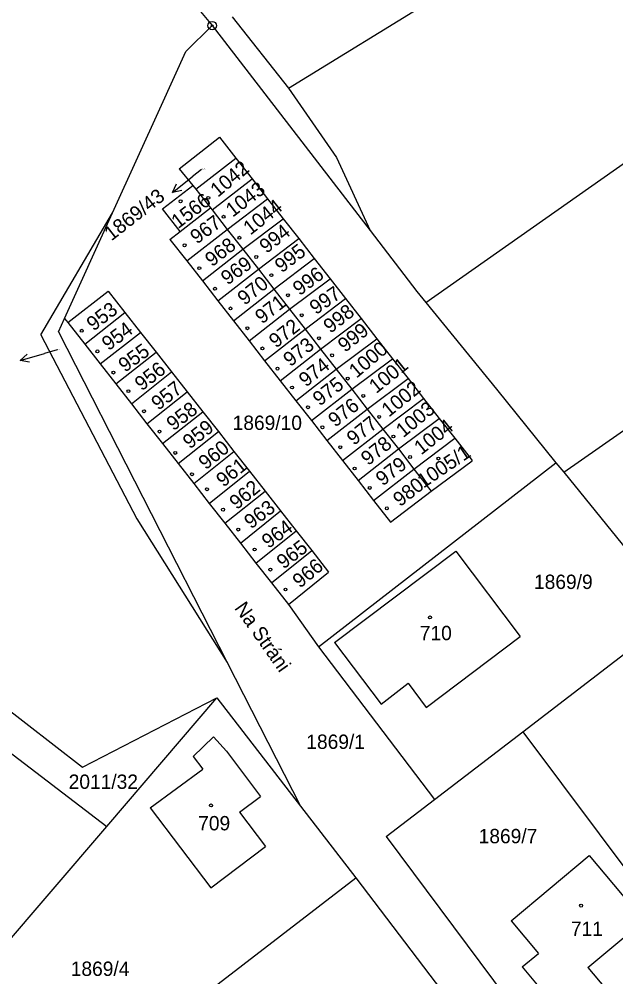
# Model space of a CAD drawing. Extents: x -763205 to -760228, y -1155311 to -1152844.
# Drawn here: x -761715.4 to -761644.6, y -1154597.9 to -1154484.3 of the extents above; entities that cross this region are included whole.
import ezdxf

# ---------------------------------------------------------------- set-up
doc = ezdxf.new("R2010")
doc.units = 0
for name, color, linetype in [('Vrstva 1', 7, 'Continuous'), ('Vrstva 15', 7, 'Continuous'), ('Vrstva 16', 7, 'Continuous'), ('Vrstva 18', 7, 'Continuous'), ('Vrstva 19', 7, 'Continuous'), ('Vrstva 24', 7, 'Continuous'), ('Vrstva 25', 7, 'Continuous'), ('Vrstva 6', 7, 'Continuous')]:
    doc.layers.add(name, color=color, linetype=linetype)

msp = doc.modelspace()

# ---------------------------------------------------------------- linework, layer by layer
at = {"layer": 'Vrstva 1'}
for p, q in [((-761717.74, -1154454.29), (-761692.49, -1154485.08)), ((-761695.63, -1154488.16), (-761692.49, -1154485.08)), ((-761692.49, -1154485.08), (-761673.78, -1154509.38)), ((-761698.5, -1154494.49), (-761695.63, -1154488.16)), ((-761704.31, -1154507.28), (-761698.5, -1154494.49)), ((-761696.42, -1154502.05), (-761691.62, -1154498.3)), ((-761691.62, -1154498.3), (-761689.69, -1154500.78)), ((-761694.43, -1154504.48), (-761689.69, -1154500.78)), ((-761689.69, -1154500.78), (-761687.77, -1154503.24)), ((-761696.42, -1154502.05), (-761694.8, -1154504.03)), ((-761692.5, -1154506.94), (-761687.77, -1154503.24)), ((-761687.77, -1154503.24), (-761685.92, -1154505.6)), ((-761698.38, -1154506.79), (-761694.8, -1154504.03)), ((-761694.8, -1154504.03), (-761694.43, -1154504.48)), ((-761694.43, -1154504.48), (-761692.69, -1154506.67)), ((-761690.7, -1154509.24), (-761685.92, -1154505.6)), ((-761685.92, -1154505.6), (-761684.08, -1154507.97)), ((-761696.28, -1154509.47), (-761698.38, -1154506.79)), ((-761696.28, -1154509.47), (-761692.69, -1154506.67)), ((-761692.69, -1154506.67), (-761692.5, -1154506.94)), ((-761692.5, -1154506.94), (-761690.7, -1154509.24)), ((-761709.98, -1154519.79), (-761704.31, -1154507.28)), ((-761688.85, -1154511.6), (-761684.08, -1154507.97)), ((-761684.08, -1154507.97), (-761682.24, -1154510.33)), ((-761697.5, -1154510.42), (-761696.28, -1154509.47)), ((-761695.5, -1154512.98), (-761690.7, -1154509.24)), ((-761690.7, -1154509.24), (-761688.85, -1154511.6)), ((-761687.01, -1154513.97), (-761682.24, -1154510.33)), ((-761682.24, -1154510.33), (-761680.4, -1154512.69)), ((-761673.78, -1154509.38), (-761668.22, -1154516.6)), ((-761697.5, -1154510.42), (-761695.5, -1154512.98)), ((-761693.66, -1154515.35), (-761688.85, -1154511.6)), ((-761688.85, -1154511.6), (-761687.01, -1154513.97)), ((-761695.5, -1154512.98), (-761693.66, -1154515.35)), ((-761685.17, -1154516.34), (-761680.4, -1154512.69)), ((-761680.4, -1154512.69), (-761678.52, -1154515.09)), ((-761691.81, -1154517.72), (-761687.01, -1154513.97)), ((-761687.01, -1154513.97), (-761685.17, -1154516.34)), ((-761693.66, -1154515.35), (-761691.81, -1154517.72)), ((-761683.32, -1154518.71), (-761678.52, -1154515.09)), ((-761678.52, -1154515.09), (-761676.68, -1154517.45)), ((-761650.83, -1154538.03), (-761619.25, -1154515.92)), ((-761709.6, -1154520.28), (-761704.83, -1154516.55)), ((-761704.83, -1154516.55), (-761702.83, -1154519.1)), ((-761689.97, -1154520.08), (-761685.17, -1154516.34)), ((-761685.17, -1154516.34), (-761683.32, -1154518.71)), ((-761668.22, -1154516.6), (-761667.18, -1154517.89)), ((-761691.81, -1154517.72), (-761689.97, -1154520.08)), ((-761681.48, -1154521.07), (-761676.68, -1154517.45)), ((-761676.68, -1154517.45), (-761674.84, -1154519.81)), ((-761667.18, -1154517.89), (-761658.81, -1154528.2)), ((-761707.6, -1154522.84), (-761702.83, -1154519.1)), ((-761702.83, -1154519.1), (-761700.99, -1154521.45)), ((-761688.12, -1154522.45), (-761683.32, -1154518.71)), ((-761683.32, -1154518.71), (-761681.48, -1154521.07)), ((-761710.7, -1154521.38), (-761709.98, -1154519.79)), ((-761709.98, -1154519.79), (-761709.6, -1154520.28)), ((-761709.6, -1154520.28), (-761707.6, -1154522.84)), ((-761689.97, -1154520.08), (-761688.12, -1154522.45)), ((-761679.64, -1154523.45), (-761674.84, -1154519.81)), ((-761674.84, -1154519.81), (-761672.96, -1154522.21)), ((-761710.7, -1154521.38), (-761690.71, -1154560.61)), ((-761705.76, -1154525.2), (-761700.99, -1154521.45)), ((-761700.99, -1154521.45), (-761699.14, -1154523.8)), ((-761686.28, -1154524.81), (-761681.48, -1154521.07)), ((-761681.48, -1154521.07), (-761679.64, -1154523.45)), ((-761707.6, -1154522.84), (-761705.76, -1154525.2)), ((-761688.12, -1154522.45), (-761686.28, -1154524.81)), ((-761677.8, -1154525.81), (-761672.96, -1154522.21)), ((-761672.96, -1154522.21), (-761671.12, -1154524.57)), ((-761703.91, -1154527.56), (-761699.14, -1154523.8)), ((-761699.14, -1154523.8), (-761697.3, -1154526.15)), ((-761684.43, -1154527.18), (-761679.64, -1154523.45)), ((-761679.64, -1154523.45), (-761677.8, -1154525.81)), ((-761686.28, -1154524.81), (-761684.43, -1154527.18)), ((-761675.95, -1154528.18), (-761671.12, -1154524.57)), ((-761671.12, -1154524.57), (-761669.28, -1154526.93)), ((-761705.76, -1154525.2), (-761703.91, -1154527.56)), ((-761702.07, -1154529.92), (-761697.3, -1154526.15)), ((-761697.3, -1154526.15), (-761695.45, -1154528.51)), ((-761682.58, -1154529.55), (-761677.8, -1154525.81)), ((-761677.8, -1154525.81), (-761675.95, -1154528.18)), ((-761684.43, -1154527.18), (-761682.58, -1154529.55)), ((-761674.11, -1154530.54), (-761669.28, -1154526.93)), ((-761669.28, -1154526.93), (-761667.43, -1154529.29)), ((-761703.91, -1154527.56), (-761702.07, -1154529.92)), ((-761700.22, -1154532.28), (-761695.45, -1154528.51)), ((-761695.45, -1154528.51), (-761693.61, -1154530.86)), ((-761680.74, -1154531.91), (-761675.95, -1154528.18)), ((-761675.95, -1154528.18), (-761674.11, -1154530.54)), ((-761658.81, -1154528.2), (-761651.74, -1154536.91)), ((-761682.58, -1154529.55), (-761680.74, -1154531.91)), ((-761672.27, -1154532.92), (-761667.43, -1154529.29)), ((-761667.43, -1154529.29), (-761665.59, -1154531.65)), ((-761702.07, -1154529.92), (-761700.22, -1154532.28)), ((-761678.89, -1154534.28), (-761674.11, -1154530.54)), ((-761674.11, -1154530.54), (-761672.27, -1154532.92)), ((-761698.38, -1154534.64), (-761693.61, -1154530.86)), ((-761693.61, -1154530.86), (-761691.76, -1154533.21)), ((-761680.74, -1154531.91), (-761678.89, -1154534.28)), ((-761670.42, -1154535.28), (-761665.59, -1154531.65)), ((-761665.59, -1154531.65), (-761663.75, -1154534.01)), ((-761700.22, -1154532.28), (-761698.38, -1154534.64)), ((-761677.05, -1154536.64), (-761672.27, -1154532.92)), ((-761672.27, -1154532.92), (-761670.42, -1154535.28)), ((-761696.53, -1154537), (-761691.76, -1154533.21)), ((-761691.76, -1154533.21), (-761689.92, -1154535.56)), ((-761668.59, -1154537.66), (-761663.75, -1154534.01)), ((-761663.75, -1154534.01), (-761661.81, -1154536.49)), ((-761698.38, -1154534.64), (-761696.53, -1154537)), ((-761678.89, -1154534.28), (-761677.05, -1154536.64)), ((-761675.2, -1154539.01), (-761670.42, -1154535.28)), ((-761670.42, -1154535.28), (-761668.59, -1154537.66)), ((-761694.68, -1154539.37), (-761689.92, -1154535.56)), ((-761689.92, -1154535.56), (-761688.08, -1154537.91)), ((-761696.53, -1154537), (-761694.68, -1154539.37)), ((-761679.9, -1154558.73), (-761651.74, -1154536.91)), ((-761677.05, -1154536.64), (-761675.2, -1154539.01)), ((-761666.55, -1154540.27), (-761661.66, -1154536.69)), ((-761661.81, -1154536.49), (-761661.66, -1154536.69)), ((-761651.74, -1154536.91), (-761650.83, -1154538.03)), ((-761692.84, -1154541.73), (-761688.08, -1154537.91)), ((-761688.08, -1154537.91), (-761686.23, -1154540.27)), ((-761673.36, -1154541.38), (-761668.59, -1154537.66)), ((-761668.59, -1154537.66), (-761666.7, -1154540.08)), ((-761650.83, -1154538.03), (-761637.32, -1154554.68)), ((-761694.68, -1154539.37), (-761692.84, -1154541.73)), ((-761675.2, -1154539.01), (-761673.36, -1154541.38)), ((-761690.99, -1154544.09), (-761686.23, -1154540.27)), ((-761686.23, -1154540.27), (-761684.39, -1154542.62)), ((-761671.36, -1154543.94), (-761666.55, -1154540.27)), ((-761666.7, -1154540.08), (-761666.55, -1154540.27)), ((-761692.84, -1154541.73), (-761690.99, -1154544.09)), ((-761673.36, -1154541.38), (-761671.36, -1154543.94)), ((-761689.15, -1154546.45), (-761684.39, -1154542.62)), ((-761684.39, -1154542.62), (-761682.54, -1154544.97)), ((-761690.99, -1154544.09), (-761689.15, -1154546.45)), ((-761687.3, -1154548.81), (-761682.54, -1154544.97)), ((-761682.54, -1154544.97), (-761680.7, -1154547.32)), ((-761689.15, -1154546.45), (-761687.3, -1154548.81)), ((-761685.46, -1154551.17), (-761680.7, -1154547.32)), ((-761680.7, -1154547.32), (-761678.7, -1154549.87)), ((-761678, -1154558.22), (-761663.63, -1154547.38)), ((-761663.63, -1154547.38), (-761655.97, -1154557.53)), ((-761687.3, -1154548.81), (-761685.46, -1154551.17)), ((-761683.46, -1154553.73), (-761678.7, -1154549.87)), ((-761685.46, -1154551.17), (-761683.46, -1154553.73)), ((-761683.46, -1154553.73), (-761679.9, -1154558.73)), ((-761655.68, -1154568.83), (-761637.32, -1154554.68)), ((-761733.71, -1154558.04), (-761705, -1154580.04)), ((-761667.14, -1154565.92), (-761655.97, -1154557.53)), ((-761679.9, -1154558.73), (-761666.15, -1154576.85)), ((-761678, -1154558.22), (-761672.48, -1154565.53)), ((-761690.71, -1154560.61), (-761682.02, -1154577.65)), ((-761672.48, -1154565.53), (-761669.28, -1154563.06)), ((-761669.28, -1154563.06), (-761667.14, -1154565.92)), ((-761705, -1154580.04), (-761691.95, -1154564.8)), ((-761691.95, -1154564.8), (-761682.02, -1154577.65)), ((-761694.73, -1154571.75), (-761692.32, -1154569.41)), ((-761692.32, -1154569.41), (-761690.79, -1154571.13)), ((-761666.15, -1154576.85), (-761655.68, -1154568.83)), ((-761655.68, -1154568.83), (-761633.18, -1154598.92)), ((-761690.79, -1154571.13), (-761686.78, -1154576.47)), ((-761694.73, -1154571.75), (-761693.62, -1154573.23)), ((-761699.83, -1154577.84), (-761693.62, -1154573.23)), ((-761689.26, -1154578.34), (-761686.78, -1154576.47)), ((-761671.88, -1154581.22), (-761666.15, -1154576.85)), ((-761699.83, -1154577.84), (-761692.66, -1154587.3)), ((-761689.26, -1154578.34), (-761686.19, -1154582.4)), ((-761682.02, -1154577.65), (-761675.46, -1154586.15)), ((-761724.52, -1154602.84), (-761705, -1154580.04)), ((-761671.88, -1154581.22), (-761651.04, -1154609.18)), ((-761692.66, -1154587.3), (-761686.19, -1154582.4)), ((-761657.04, -1154591.24), (-761647.79, -1154583.5)), ((-761647.79, -1154583.5), (-761641.34, -1154591.22)), ((-761693.32, -1154599.87), (-761675.46, -1154586.15)), ((-761675.46, -1154586.15), (-761655.51, -1154612.37)), ((-761657.04, -1154591.24), (-761653.83, -1154595.1)), ((-761647.97, -1154596.76), (-761641.34, -1154591.22)), ((-761655.75, -1154596.7), (-761653.83, -1154595.1)), ((-761655.75, -1154596.7), (-761650.4, -1154603.03)), ((-761647.97, -1154596.76), (-761645.89, -1154599.26))]:
    msp.add_line(p, q, dxfattribs=at)
at = {"layer": 'Vrstva 16'}
for p, q in [((-761693.76, -1154502.12), (-761694.85, -1154502.99)), ((-761697.197, -1154504.858), (-761694.85, -1154502.99)), ((-761715.265, -1154524.794), (-761712.38, -1154523.97)), ((-761710.85, -1154523.53), (-761712.38, -1154523.97))]:
    msp.add_line(p, q, dxfattribs=at)
for points in [[(-761696.104, -1154504.627), (-761697.197, -1154504.858), (-761696.726, -1154503.844)], [(-761714.166, -1154525), (-761715.265, -1154524.794), (-761714.44, -1154524.038)]]:
    msp.add_lwpolyline(points, dxfattribs=at)
at = {"layer": 'Vrstva 24'}
for radius in [0.5, 0.1]:
    msp.add_circle((-761692.49, -1154485.08), radius, dxfattribs=at)
at = {"layer": 'Vrstva 25'}
for centre in [(-761696.24, -1154505.91), (-761692.95, -1154505.5), (-761691.14, -1154507.74), (-761689.26, -1154510.23), (-761695.76, -1154511.13), (-761687.27, -1154512.51), (-761694.02, -1154513.84), (-761685.48, -1154514.67), (-761692.16, -1154516.28), (-761683.52, -1154517.05), (-761690.32, -1154518.61), (-761681.87, -1154519.42), (-761707.95, -1154521.26), (-761688.31, -1154520.96), (-761679.84, -1154522.15), (-761706.1, -1154523.7), (-761686.54, -1154523.35), (-761678.28, -1154524.17), (-761704.2, -1154526.22), (-761684.75, -1154525.75), (-761676.42, -1154526.93), (-761702.42, -1154528.42), (-761683.03, -1154527.99), (-761674.59, -1154528.99), (-761700.57, -1154530.8), (-761681.14, -1154530.33), (-761672.7, -1154531.48), (-761698.74, -1154533.22), (-761679.43, -1154532.71), (-761671.01, -1154533.8), (-761677.31, -1154535.07), (-761696.87, -1154535.74), (-761669.04, -1154536.23), (-761665.68, -1154536.41), (-761675.62, -1154537.59), (-761694.89, -1154538.27), (-761693.11, -1154540.05), (-761673.82, -1154539.89), (-761671.79, -1154542.32), (-761691.21, -1154542.47), (-761689.4, -1154544.84), (-761687.46, -1154547.2), (-761685.6, -1154549.58), (-761683.8, -1154551.94), (-761666.68, -1154555.25), (-761692.63, -1154577.55), (-761648.76, -1154589.43)]:
    msp.add_circle(centre, 0.175, dxfattribs=at)
at = {"layer": 'Vrstva 6'}
for p, q in [((-761683.46, -1154492.5), (-761628.48, -1154458.64)), ((-761690.11, -1154484.04), (-761683.46, -1154492.5)), ((-761683.46, -1154492.5), (-761677.75, -1154500.7)), ((-761667.18, -1154517.89), (-761633.85, -1154494.49)), ((-761677.75, -1154500.7), (-761673.78, -1154509.38)), ((-761712.8, -1154521.75), (-761704.31, -1154507.28)), ((-761712.8, -1154521.75), (-761701.41, -1154543.55)), ((-761701.41, -1154543.55), (-761690.71, -1154560.61)), ((-761742.65, -1154546.11), (-761707.88, -1154572.99)), ((-761707.88, -1154572.99), (-761691.95, -1154564.8))]:
    msp.add_line(p, q, dxfattribs=at)

# ---------------------------------------------------------------- texts
at = {"layer": 'Vrstva 15'}
msp.add_text('Na Stráni', height=1.7, rotation=305.21462, dxfattribs=at).set_placement((-761689.924, -1154554.152))
at = {"layer": 'Vrstva 16'}
msp.add_text('1869/43', height=1.7, rotation=37.9871, dxfattribs=at).set_placement((-761704.437, -1154510.671))
at = {"layer": 'Vrstva 18'}
for s, height, p in [('1869/43', 0.1, (-761693.737, -1154502.12)), ('1870', 0.1, (-761710.827, -1154523.53)), ('1869/10', 1.7, (-761690.067, -1154533.02)), ('1869/9', 1.7, (-761654.347, -1154551.88)), ('1869/1', 1.7, (-761681.337, -1154570.84)), ('2011/32', 1.7, (-761709.503, -1154575.58)), ('1869/7', 1.7, (-761660.907, -1154582.03)), ('1869/4', 1.7, (-761709.257, -1154597.76))]:
    msp.add_text(s, height=height, dxfattribs=at).set_placement(p)
at = {"layer": 'Vrstva 19'}
for s, rotation, p in [('1042', 39.87786, (-761691.829, -1154505.508)), ('1043', 37.29955, (-761690.068, -1154507.862)), ('1566', 37.29955, (-761696.523, -1154509.219)), ('1044', 38.21629, (-761687.971, -1154509.987)), ('967', 36.26823, (-761694.309, -1154511.05)), ('994', 38.27358, (-761686.054, -1154512.163)), ('968', 37.92981, (-761692.513, -1154513.744)), ('995', 37.24226, (-761684.261, -1154514.466)), ('969', 35.98175, (-761690.678, -1154515.911)), ('996', 36.6693, (-761682.14, -1154517.168)), ('970', 38.27358, (-761688.654, -1154518.313)), ('997', 34.49206, (-761680.204, -1154519.416)), ('971', 37.9871, (-761686.583, -1154520.524)), ('953', 37.35685, (-761706.561, -1154521.366)), ('998', 37.81521, (-761678.482, -1154521.634)), ('954', 36.49741, (-761704.779, -1154523.689)), ('972', 37.9871, (-761684.933, -1154523.384)), ('999', 38.73195, (-761676.745, -1154523.891)), ('955', 35.98175, (-761702.828, -1154526.251)), ('973', 38.21629, (-761683.233, -1154525.593)), ('1000', 40.27893, (-761675.39, -1154526.956)), ('956', 37.70062, (-761700.852, -1154528.465)), ('974', 38.21629, (-761681.383, -1154528.003)), ('1001', 38.67465, (-761673.053, -1154528.775)), ('957', 37.81521, (-761698.882, -1154530.764)), ('975', 37.58603, (-761679.752, -1154530.255)), ('1002', 39.07572, (-761671.555, -1154531.572)), ('976', 37.87251, (-761677.913, -1154532.764)), ('958', 37.29955, (-761697.091, -1154533.196)), ('1003', 39.30491, (-761669.846, -1154534.011)), ('959', 38.0444, (-761695.143, -1154535.354)), ('977', 38.38817, (-761675.704, -1154534.933)), ('1004', 38.10169, (-761667.721, -1154536.048)), ('978', 38.56006, (-761674.014, -1154537.322)), ('960', 38.96113, (-761693.255, -1154537.821)), ('1005/1', 34.20558, (-761667.447, -1154539.983)), ('979', 37.64333, (-761672.282, -1154539.735)), ('961', 38.78924, (-761691.165, -1154539.881)), ('980', 37.9871, (-761670.223, -1154542.194)), ('962', 39.47679, (-761689.577, -1154542.549)), ('963', 36.72659, (-761687.9, -1154544.828)), ('964', 36.15364, (-761685.838, -1154547.15)), ('965', 37.24226, (-761684.041, -1154549.586)), ('966', 39.76327, (-761682.088, -1154551.858))]:
    msp.add_text(s, height=1.7, rotation=rotation, dxfattribs=at).set_placement(p)
for s, p in [('710', (-761667.883, -1154557.95)), ('709', (-761694.153, -1154580.5)), ('711', (-761649.973, -1154593.02))]:
    msp.add_text(s, height=1.7, dxfattribs=at).set_placement(p)

doc.saveas('drawing.dxf')
